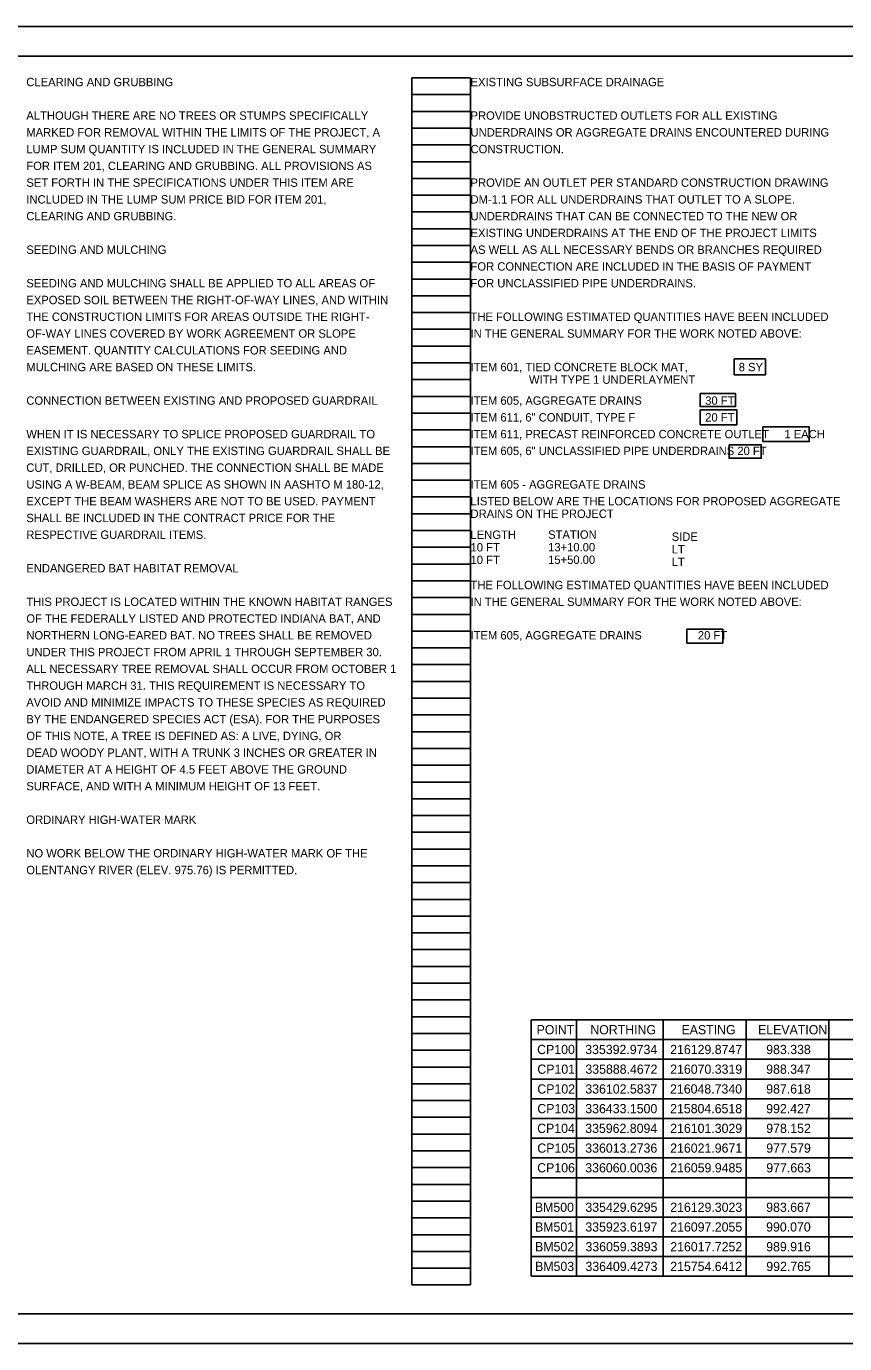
# Model space of a CAD drawing. Extents: x -10.1 to 34, y -4.5 to 22.
# Drawn here: x 9.82 to 23.49, y 0 to 22 of the extents above; entities that cross this region are included whole.
import ezdxf

# ---------------------------------------------------------------- set-up
doc = ezdxf.new("R2010")
doc.units = 0
for name, color, linetype in [('Default', 7, 'Continuous'), ('SH_Border', 7, 'Continuous'), ('SH_Cut_Line', 7, 'Continuous'), ('SH_Data', 7, 'Continuous'), ('SH_Text', 7, 'Continuous')]:
    doc.layers.add(name, color=color, linetype=linetype)

msp = doc.modelspace()

# ---------------------------------------------------------------- linework, layer by layer
at = {"layer": 'Default'}
for p, q in [((18.251, 5.407), (28.529, 5.407)), ((18.251, 5.407), (18.251, 1.125)), ((19.009, 5.407), (19.009, 1.125)), ((20.458, 5.407), (20.458, 1.125)), ((21.842, 5.407), (21.842, 1.125)), ((23.226, 5.407), (23.226, 1.125)), ((18.251, 5.078), (28.529, 5.078)), ((18.251, 4.749), (28.529, 4.749)), ((18.251, 4.419), (28.529, 4.419)), ((18.251, 4.09), (28.529, 4.09)), ((18.251, 3.76), (28.529, 3.76)), ((18.251, 3.431), (28.529, 3.431)), ((18.251, 3.102), (28.529, 3.102)), ((18.251, 2.772), (28.529, 2.772)), ((18.251, 2.443), (28.529, 2.443)), ((18.251, 2.113), (28.529, 2.113)), ((18.251, 1.784), (28.529, 1.784)), ((18.251, 1.454), (28.529, 1.454)), ((18.251, 1.125), (28.529, 1.125))]:
    msp.add_line(p, q, dxfattribs=at)
at = {"layer": 'SH_Cut_Line'}
for p, q in [((16.26, 0.98), (16.26, 21.14)), ((16.26, 21.14), (17.24, 21.14)), ((17.24, 0.98), (17.24, 21.14)), ((16.26, 20.86), (17.24, 20.86)), ((16.26, 20.58), (17.24, 20.58)), ((16.26, 20.3), (17.24, 20.3)), ((16.26, 20.02), (17.24, 20.02)), ((16.26, 19.74), (17.24, 19.74)), ((16.26, 19.46), (17.24, 19.46)), ((16.26, 19.18), (17.24, 19.18)), ((16.26, 18.9), (17.24, 18.9)), ((16.26, 18.62), (17.24, 18.62)), ((16.26, 18.34), (17.24, 18.34)), ((16.26, 18.06), (17.24, 18.06)), ((16.26, 17.78), (17.24, 17.78)), ((16.26, 17.5), (17.24, 17.5)), ((16.26, 17.22), (17.24, 17.22)), ((16.26, 16.94), (17.24, 16.94)), ((16.26, 16.66), (17.24, 16.66)), ((16.26, 16.38), (17.24, 16.38)), ((16.26, 16.1), (17.24, 16.1)), ((16.26, 15.82), (17.24, 15.82)), ((16.26, 15.54), (17.24, 15.54)), ((16.26, 15.26), (17.24, 15.26)), ((16.26, 14.98), (17.24, 14.98)), ((16.26, 14.7), (17.24, 14.7)), ((16.26, 14.42), (17.24, 14.42)), ((16.26, 14.14), (17.24, 14.14)), ((16.26, 13.86), (17.24, 13.86)), ((16.26, 13.58), (17.24, 13.58)), ((16.26, 13.3), (17.24, 13.3)), ((16.26, 13.02), (17.24, 13.02)), ((16.26, 12.74), (17.24, 12.74)), ((16.26, 12.46), (17.24, 12.46)), ((16.26, 12.18), (17.24, 12.18)), ((16.26, 11.9), (17.24, 11.9)), ((16.26, 11.62), (17.24, 11.62)), ((16.26, 11.34), (17.24, 11.34)), ((16.26, 11.06), (17.24, 11.06)), ((16.26, 10.78), (17.24, 10.78)), ((16.26, 10.5), (17.24, 10.5)), ((16.26, 10.22), (17.24, 10.22)), ((16.26, 9.94), (17.24, 9.94)), ((16.26, 9.66), (17.24, 9.66)), ((16.26, 9.38), (17.24, 9.38)), ((16.26, 9.1), (17.24, 9.1)), ((16.26, 8.82), (17.24, 8.82)), ((16.26, 8.54), (17.24, 8.54)), ((16.26, 8.26), (17.24, 8.26)), ((16.26, 7.98), (17.24, 7.98)), ((16.26, 7.7), (17.24, 7.7)), ((16.26, 7.42), (17.24, 7.42)), ((16.26, 7.14), (17.24, 7.14)), ((16.26, 6.86), (17.24, 6.86)), ((16.26, 6.58), (17.24, 6.58)), ((16.26, 6.3), (17.24, 6.3)), ((16.26, 6.02), (17.24, 6.02)), ((16.26, 5.74), (17.24, 5.74)), ((16.26, 5.46), (17.24, 5.46)), ((16.26, 5.18), (17.24, 5.18)), ((16.26, 4.9), (17.24, 4.9)), ((16.26, 4.62), (17.24, 4.62)), ((16.26, 4.34), (17.24, 4.34)), ((16.26, 4.06), (17.24, 4.06)), ((16.26, 3.78), (17.24, 3.78)), ((16.26, 3.5), (17.24, 3.5)), ((16.26, 3.22), (17.24, 3.22)), ((16.26, 2.94), (17.24, 2.94)), ((16.26, 2.66), (17.24, 2.66)), ((16.26, 2.38), (17.24, 2.38)), ((16.26, 2.1), (17.24, 2.1)), ((16.26, 1.82), (17.24, 1.82)), ((16.26, 1.54), (17.24, 1.54)), ((16.26, 1.26), (17.24, 1.26)), ((16.26, 0.98), (17.24, 0.98))]:
    msp.add_line(p, q, dxfattribs=at)
for points in [[(21.644, 16.447), (22.165, 16.447), (22.165, 16.178), (21.644, 16.178)], [(21.076, 15.868), (21.668, 15.868), (21.668, 15.649), (21.076, 15.649)], [(21.074, 15.597), (21.688, 15.597), (21.688, 15.347), (21.074, 15.347)], [(22.124, 15.309), (22.899, 15.309), (22.899, 15.064), (22.124, 15.064)], [(21.558, 15.011), (22.096, 15.011), (22.096, 14.788), (21.558, 14.788)], [(20.854, 11.934), (21.452, 11.934), (21.452, 11.7), (20.854, 11.7)]]:
    msp.add_lwpolyline(points, close=True, dxfattribs=at)
at = {"layer": 'SH_Data'}
msp.add_lwpolyline([(1.5, 21.5), (33.5, 21.5), (33.5, 0.5), (1.5, 0.5)], close=True, dxfattribs=at)
at = {"layer": 'SH_Text'}
msp.add_lwpolyline([(0, 0), (34, 0), (34, 22), (0, 22)], close=True, dxfattribs=at)

# ---------------------------------------------------------------- texts
at = {"layer": 'Default'}
for s, p in [('POINT', (18.344, 5.166)), ('NORTHING', (19.241, 5.166)), ('EASTING', (20.764, 5.166)), ('ELEVATION', (22.043, 5.166)), ('CP100', (18.353, 4.836)), ('335392.9734', (19.156, 4.836)), ('216129.8747', (20.575, 4.836)), ('983.338', (22.179, 4.836)), ('CP101', (18.356, 4.507)), ('335888.4672', (19.159, 4.507)), ('216070.3319', (20.575, 4.507)), ('988.347', (22.179, 4.507)), ('CP102', (18.356, 4.177)), ('336102.5837', (19.158, 4.177)), ('216048.7340', (20.573, 4.177)), ('987.618', (22.179, 4.177)), ('CP103', (18.356, 3.848)), ('336433.1500', (19.157, 3.848)), ('215804.6518', (20.574, 3.848)), ('992.427', (22.179, 3.848)), ('CP104', (18.353, 3.519)), ('335962.8094', (19.156, 3.519)), ('216101.3029', (20.575, 3.519)), ('978.152', (22.18, 3.519)), ('CP105', (18.356, 3.189)), ('336013.2736', (19.157, 3.189)), ('216021.9671', (20.575, 3.189)), ('977.579', (22.18, 3.189)), ('CP106', (18.354, 2.86)), ('336060.0036', (19.157, 2.86)), ('216059.9485', (20.576, 2.86)), ('977.663', (22.181, 2.86)), ('BM500', (18.315, 2.201)), ('335429.6295', (19.159, 2.201)), ('216129.3023', (20.576, 2.201)), ('983.667', (22.179, 2.201)), ('BM501', (18.317, 1.872)), ('335923.6197', (19.158, 1.872)), ('216097.2055', (20.576, 1.872)), ('990.070', (22.178, 1.872)), ('BM502', (18.318, 1.542)), ('336059.3893', (19.16, 1.542)), ('216017.7252', (20.576, 1.542)), ('989.916', (22.179, 1.542)), ('BM503', (18.318, 1.213)), ('336409.4273', (19.16, 1.213)), ('215754.6412', (20.576, 1.213)), ('992.765', (22.181, 1.213))]:
    msp.add_text(s, height=0.154, dxfattribs=at).set_placement(p)
at = {"layer": 'SH_Border'}
for s, p in [('CLEARING AND GRUBBING', (9.82, 21)), ('EXISTING SUBSURFACE DRAINAGE', (17.24, 21)), ('ALTHOUGH THERE ARE NO TREES OR STUMPS SPECIFICALLY', (9.82, 20.44)), ('PROVIDE UNOBSTRUCTED OUTLETS FOR ALL EXISTING', (17.24, 20.44)), ('MARKED FOR REMOVAL WITHIN THE LIMITS OF THE PROJECT, A', (9.82, 20.16)), ('UNDERDRAINS OR AGGREGATE DRAINS ENCOUNTERED DURING', (17.24, 20.16)), ('LUMP SUM QUANTITY IS INCLUDED IN THE GENERAL SUMMARY', (9.82, 19.88)), ('CONSTRUCTION.', (17.24, 19.88)), ('FOR ITEM 201, CLEARING AND GRUBBING. ALL PROVISIONS AS', (9.82, 19.6)), ('SET FORTH IN THE SPECIFICATIONS UNDER THIS ITEM ARE', (9.82, 19.32)), ('PROVIDE AN OUTLET PER STANDARD CONSTRUCTION DRAWING', (17.24, 19.32)), ('INCLUDED IN THE LUMP SUM PRICE BID FOR ITEM 201,', (9.82, 19.04)), ('DM-1.1 FOR ALL UNDERDRAINS THAT OUTLET TO A SLOPE.', (17.24, 19.04)), ('CLEARING AND GRUBBING.', (9.82, 18.76)), ('UNDERDRAINS THAT CAN BE CONNECTED TO THE NEW OR', (17.24, 18.76)), ('EXISTING UNDERDRAINS AT THE END OF THE PROJECT LIMITS', (17.24, 18.48)), ('SEEDING AND MULCHING', (9.82, 18.2)), ('AS WELL AS ALL NECESSARY BENDS OR BRANCHES REQUIRED', (17.24, 18.2)), ('FOR CONNECTION ARE INCLUDED IN THE BASIS OF PAYMENT', (17.24, 17.92)), ('SEEDING AND MULCHING SHALL BE APPLIED TO ALL AREAS OF', (9.82, 17.64)), ('FOR UNCLASSIFIED PIPE UNDERDRAINS.', (17.24, 17.64)), ('EXPOSED SOIL BETWEEN THE RIGHT-OF-WAY LINES, AND WITHIN', (9.82, 17.36)), ('THE CONSTRUCTION LIMITS FOR AREAS OUTSIDE THE RIGHT-', (9.82, 17.08)), ('THE FOLLOWING ESTIMATED QUANTITIES HAVE BEEN INCLUDED', (17.24, 17.08)), ('OF-WAY LINES COVERED BY WORK AGREEMENT OR SLOPE', (9.82, 16.8)), ('IN THE GENERAL SUMMARY FOR THE WORK NOTED ABOVE:', (17.24, 16.8)), ('EASEMENT. QUANTITY CALCULATIONS FOR SEEDING AND', (9.82, 16.52)), ('MULCHING ARE BASED ON THESE LIMITS.', (9.82, 16.24)), ('ITEM 601, TIED CONCRETE BLOCK MAT, ', (17.24, 16.24)), ('8 SY', (21.72, 16.24)), ('        WITH TYPE 1 UNDERLAYMENT', (17.8, 16.03)), ('CONNECTION BETWEEN EXISTING AND PROPOSED GUARDRAIL', (9.82, 15.68)), ('ITEM 605, AGGREGATE DRAINS                  ', (17.24, 15.68)), ('30 FT', (21.16, 15.68)), ('ITEM 611, 6" CONDUIT, TYPE F             ', (17.24, 15.4)), ('20 FT', (21.16, 15.4)), ('WHEN IT IS NECESSARY TO SPLICE PROPOSED GUARDRAIL TO', (9.82, 15.12)), ('ITEM 611, PRECAST REINFORCED CONCRETE OUTLET     1 EACH', (17.24, 15.12)), ('EXISTING GUARDRAIL, ONLY THE EXISTING GUARDRAIL SHALL BE', (9.82, 14.84)), ('ITEM 605, 6" UNCLASSIFIED PIPE UNDERDRAINS 20 FT', (17.24, 14.84)), ('CUT, DRILLED, OR PUNCHED. THE CONNECTION SHALL BE MADE', (9.82, 14.56)), ('USING A W-BEAM, BEAM SPLICE AS SHOWN IN AASHTO M 180-12,', (9.82, 14.28)), ('ITEM 605 - AGGREGATE DRAINS', (17.24, 14.28)), ('EXCEPT THE BEAM WASHERS ARE NOT TO BE USED. PAYMENT', (9.82, 14)), ('LISTED BELOW ARE THE LOCATIONS FOR PROPOSED AGGREGATE', (17.24, 14)), ('SHALL BE INCLUDED IN THE CONTRACT PRICE FOR THE', (9.82, 13.72)), ('DRAINS ON THE PROJECT', (17.24, 13.79)), ('RESPECTIVE GUARDRAIL ITEMS.', (9.82, 13.44)), ('LENGTH', (17.24, 13.44)), ('STATION ', (18.536, 13.442)), ('SIDE', (20.6, 13.407)), ('10 FT', (17.24, 13.23)), ('13+10.00', (18.536, 13.232)), ('LT', (20.6, 13.197)), ('ENDANGERED BAT HABITAT REMOVAL', (9.82, 12.88)), ('10 FT', (17.24, 13.02)), ('15+50.00', (18.536, 13.022)), ('LT', (20.6, 12.987)), ('THE FOLLOWING ESTIMATED QUANTITIES HAVE BEEN INCLUDED', (17.24, 12.6)), ('THIS PROJECT IS LOCATED WITHIN THE KNOWN HABITAT RANGES', (9.82, 12.32)), ('IN THE GENERAL SUMMARY FOR THE WORK NOTED ABOVE:', (17.24, 12.32)), ('OF THE FEDERALLY LISTED AND PROTECTED INDIANA BAT, AND', (9.82, 12.04)), ('NORTHERN LONG-EARED BAT. NO TREES SHALL BE REMOVED', (9.82, 11.76)), ('ITEM 605, AGGREGATE DRAINS                  20 FT', (17.24, 11.76)), ('UNDER THIS PROJECT FROM APRIL 1 THROUGH SEPTEMBER 30.', (9.82, 11.48)), ('ALL NECESSARY TREE REMOVAL SHALL OCCUR FROM OCTOBER 1', (9.82, 11.2)), ('THROUGH MARCH 31. THIS REQUIREMENT IS NECESSARY TO', (9.82, 10.92)), ('AVOID AND MINIMIZE IMPACTS TO THESE SPECIES AS REQUIRED', (9.82, 10.64)), ('BY THE ENDANGERED SPECIES ACT (ESA). FOR THE PURPOSES', (9.82, 10.36)), ('OF THIS NOTE, A TREE IS DEFINED AS: A LIVE, DYING, OR', (9.82, 10.08)), ('DEAD WOODY PLANT, WITH A TRUNK 3 INCHES OR GREATER IN', (9.82, 9.8)), ('DIAMETER AT A HEIGHT OF 4.5 FEET ABOVE THE GROUND', (9.82, 9.52)), ('SURFACE, AND WITH A MINIMUM HEIGHT OF 13 FEET.', (9.82, 9.24)), ('ORDINARY HIGH-WATER MARK', (9.82, 8.68)), ('NO WORK BELOW THE ORDINARY HIGH-WATER MARK OF THE', (9.82, 8.12)), ('OLENTANGY RIVER (ELEV. 975.76) IS PERMITTED.', (9.82, 7.84))]:
    msp.add_text(s, height=0.14, dxfattribs=at).set_placement(p)

doc.saveas('drawing.dxf')
